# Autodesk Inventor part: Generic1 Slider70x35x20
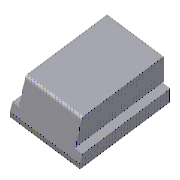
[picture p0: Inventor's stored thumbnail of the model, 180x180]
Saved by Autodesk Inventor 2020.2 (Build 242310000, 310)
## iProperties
Manager: www.cadconsulting.pl
Company: Fabian Stasiak CAD Consulting
Created: 2014-02
Part Number: Generic1 Slider70x35x20
Material: DIN 1.2343
Description: Slider
Document SubType Name: Modeling
Designer: F.Stasiak
Standard Revision: 1
Manufacturer: Generic
Language: pl-PL
Size Designation: 70x35x20
Categories: <MemberInstance><Categories><Category DisplayName="Forma wtryskowa" InternalName="349578f2-f4d4-4954-8c09-8e99297a61c0" Mnemonic="MOLD"><Category DisplayName="K
Density: 7.85 g/cm^3
Appearance: Sky Blue Dark
Catalog Web Link: www.expertbooks.pl
IsCustomPart: 1
Author: F.Stasiak
Subject: Zbiór ćwiczeń. Autodesk Inventor 2020. Kurs Professional
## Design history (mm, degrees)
sketch "Sketch1"
  geometry: L1 (0, -24)-(0, 4) reference; L2 (0, 0)-(-17.5, 0); L3 (-17.5, 0)-(-17.5, -15.5); L4 (-17.5, -15.5)-(-17, -15.5); L5 (-17, -15.5)-(-17, -16); L6 (-17, -16)-(-22, -16); L7 (-22, -16)-(-22, -20); L8 (-22, -20)-(0, -20); L9 (0, 0)-(17.5, 0); L10 (17.5, 0)-(17.5, -15.5); L11 (17.5, -15.5)-(17, -15.5); L12 (17, -15.5)-(17, -16); L13 (17, -16)-(22, -16); L14 (22, -16)-(22, -20); L15 (22, -20)-(0, -20)
  constraints: 28 end point, 6 symmetric about line, 4 parallel, 3 perpendicular, 1 point on line
  dimensions: "d1" = 35 diameter of L3 L1 (= SL_b1); "d2" = 20 distance between parallel lines of L8 L2 (= SL_h1); "d3" = 44 diameter of L7 L1 (= SL_b2); "d4" = 0.5 distance of L4.end L5.end (= REF_SL1); "d5" = 0.5 distance of L3.end L4.end (= REF_SL1); "d6" = 4 distance between parallel lines of L8 L6 (= SL_h2)
extrude "Extrusion1" new body sketch "Sketch1" distance "d7" = 70 (= SL_l1); taper "d8" = 0 deg
sketch "Sketch2"
  geometry: L1 (-70, -20)-(-70, -16) reference; L2 (-70, -18.5)-(-63.267, 0); L3 (-70, -15.5)-(-70, 0) reference; L4 (0, 0)-(-70, 0) reference; L5 (-70, -18.5)-(-70, 0); L6 (-70, 0)-(-63.267, 0)
  constraints: 6 end point, 2 point on line, 1 collinear, 1 perpendicular
  dimensions: "d9" = 20 deg angle of L3 L2 (= SL_ang); "d10" = 1.5 distance of L1.start L2.start (= SL_h3)
extrude "Extrusion2" cut sketch "Sketch2" stored distance "d11" = 44 (= SL_b2); taper "d12" = 0 deg
fillet "Fillet1" dims "d123" = 0.5 (= REF_SL1)
fillet "Fillet2" dims "d125" = 1.5 (= SL_r)
node "SL_AP"
  workplane "Work Plane1"
node "SL_GS"
node "SL_GSl"
node "SL_GSr"
node "SL_SP"
node "SL_WP"
feature "Stitch Surface1" dims "d124" = 0.254 (derived)
node "Płaszczyzna konstrukcyjna15"
feature "Rzeźbienie2"
body "Solid1"
sketch "Sketch3"
  geometry: L1 (-16, -22)-(-20, -22); L2 (-20, 0)-(-20, 22.5); L3 (-20, 22.5)-(-16, 22.5); L4 (-16, 22.5)-(-16, 18.5); L5 (-16, 18.5)-(0, 18.5); L6 (0, 18.5)-(0, -0.659); L7 (-14.748, 0)-(3.452, 0); L8 (-20, 0)-(-20, -22.5); L9 (-20, -22.5)-(-16, -22.5); L10 (-16, -22.5)-(-16, -18.5); L11 (-16, -18.5)-(0, -18.5); L12 (0, -18.5)-(0, -0.659); L13 (-20, 22)-(-16, 22) reference; L14 (-15.5, 17.5)-(0, 17.5) reference; L15 (0, 17.5)-(0, -17.5) reference; L16 (-20, -22)-(-20, 22) reference; L17 (-16, 22)-(-16, 17) reference; 3 further points
  constraints: 24 end point, 4 symmetric about line, 3 midpoint, 2 perpendicular, 2 point on line, 2 vertical
  dimensions: "d112" = 0.5 distance between parallel lines of L13 L3 (= REF_SL1); "d113" = 1 distance between parallel lines of L14 L5 (= REF_SL3); "d114" = 0 distance between parallel lines of L6 L15
body "Srf1"
body "Srf2"
body "Srf3"
body "Srf4"
extrude_surface "ExtrusionSrf1" dims "d90" = 170 (= SL_esl1 + SL_l1), "d91" = 0
patch "Boundary Patch1" dims "d100" = 0, "d115" = 0, "d116" = 0, "d117" = 0, "d118" = 0, "d119" = 0, "d120" = 0, "d121" = 0, "d122" = 0
patch "Boundary Patch2" dims "d101" = 0, "d102" = 0, "d103" = 0, "d104" = 0, "d105" = 0, "d106" = 0, "d107" = 0, "d108" = 0, "d109" = 0
feature "Powierzchnia2"
body "Srf6"
other parameters: "SL_ang" = 20 deg [user parameter; used in 1 equation term], "SL_h1" = 20 [user parameter; used in 1 equation term], "SL_l1" = 70 [user parameter; used in 3 equation terms], "SL_b1" = 35 [user parameter; used in 1 equation term], "SL_h2" = 4 [user parameter; used in 1 equation term], "SL_h3" = 1.5 [user parameter; used in 1 equation term], "SL_b2" = 44 [user parameter; used in 2 equation terms], "SL_r" = 1.5 [user parameter; used in 1 equation term], "SL_AP_ang" = 18 deg [user parameter; used in 1 equation term], "d62" = 0, "d64" = 0, "d66" = 180 deg, "d67" = 18 deg (= SL_AP_ang), "d68" = 35 (= 0.5 x SL_l1), "d70" = 180 deg, "d71" = 0, "SL_esr" = 2.5 [user parameter], "SL_esl1" = 100 [user parameter; used in 1 equation term], "REF_SL1" = 0.5 [user parameter; used in 4 equation terms], "REF_SL2" = 1 [user parameter], "REF_SL3" = 1 [user parameter; used in 1 equation term]
